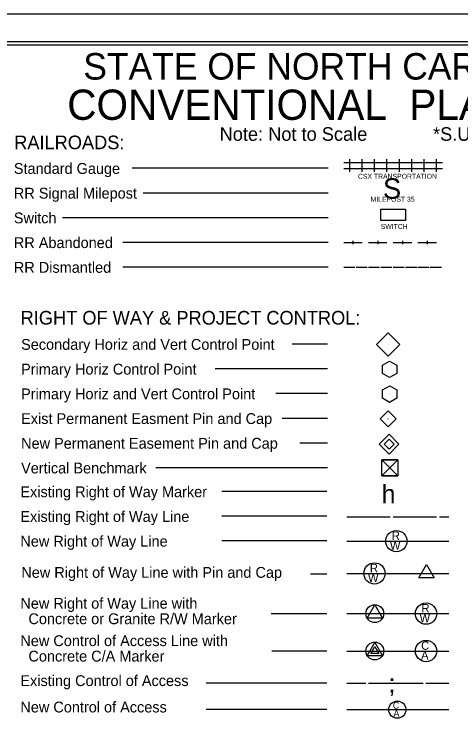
# Model space of a CAD drawing. Extents: x 2014488 to 2016172, y 399324 to 400424.
# Drawn here: x 2015050 to 2015411, y 399854 to 400424 of the extents above; entities that cross this region are included whole.
import ezdxf

# ---------------------------------------------------------------- set-up
doc = ezdxf.new("R2010")
doc.units = 0
for name, color, linetype in [('Prop ROW Permanent Easement CELL', 7, 'Continuous'), ('Sheet Plot Border Inside CELL', 7, 'Continuous'), ('Sheet Plot Border Outside CELL', 7, 'Continuous'), ('Sheet Symbology CELL', 7, 'Continuous'), ('Sheet Title CELL', 7, 'Continuous')]:
    doc.layers.add(name, color=color, linetype=linetype)

msp = doc.modelspace()

# ---------------------------------------------------------------- linework, layer by layer
at = {"layer": 'Prop ROW Permanent Easement CELL'}
msp.add_line((2015352.51, 400076.47), (2015352.51, 400076.47), dxfattribs=at)
for points in [[(2015352.51, 400084.52), (2015360.56, 400076.47), (2015352.51, 400068.42), (2015344.46, 400076.47)], [(2015352.51, 400080.5), (2015356.53, 400076.47), (2015352.51, 400072.45), (2015348.48, 400076.47)]]:
    msp.add_lwpolyline(points, close=True, dxfattribs=at)
at = {"layer": 'Sheet Plot Border Inside CELL'}
msp.add_lwpolyline([(2014500.85, 399346.86), (2016167.35, 399346.86), (2016167.35, 400401.96), (2014500.85, 400401.96)], close=True, dxfattribs=at)
at = {"layer": 'Sheet Plot Border Outside CELL'}
msp.add_lwpolyline([(2014487.85, 399324.41), (2016171.85, 399324.41), (2016171.85, 400424.41), (2014487.85, 400424.41)], close=True, dxfattribs=at)
at = {"layer": 'Sheet Symbology CELL'}
for p, q in [((2015315.85, 400304.44), (2015325.85, 400304.44)), ((2015320.85, 400296.94), (2015320.85, 400306.94)), ((2015325.85, 400304.44), (2015335.85, 400304.44)), ((2015330.85, 400296.94), (2015330.85, 400306.94)), ((2015335.85, 400304.44), (2015345.85, 400304.44)), ((2015340.85, 400296.94), (2015340.85, 400306.94)), ((2015345.85, 400304.44), (2015355.85, 400304.44)), ((2015350.85, 400296.94), (2015350.85, 400306.94)), ((2015355.85, 400304.44), (2015365.85, 400304.44)), ((2015360.85, 400296.94), (2015360.85, 400306.94)), ((2015365.85, 400304.44), (2015375.85, 400304.44)), ((2015370.85, 400296.94), (2015370.85, 400306.94)), ((2015375.85, 400304.44), (2015385.85, 400304.44)), ((2015380.85, 400296.94), (2015380.85, 400306.94)), ((2015385.85, 400304.44), (2015395.85, 400304.44)), ((2015390.85, 400296.94), (2015390.85, 400306.94)), ((2015303.45, 400299.68), (2015145.04, 400299.68)), ((2015315.85, 400299.44), (2015325.85, 400299.44)), ((2015325.85, 400299.44), (2015335.85, 400299.44)), ((2015335.85, 400299.44), (2015345.85, 400299.44)), ((2015345.85, 400299.44), (2015355.85, 400299.44)), ((2015355.85, 400299.44), (2015365.85, 400299.44)), ((2015365.85, 400299.44), (2015375.85, 400299.44)), ((2015375.85, 400299.44), (2015385.85, 400299.44)), ((2015385.85, 400299.44), (2015395.85, 400299.44)), ((2015303.45, 400279.68), (2015153.9, 400279.68)), ((2015303.45, 400259.68), (2015088.54, 400259.68)), ((2015303.45, 400239.68), (2015137.29, 400239.68)), ((2015315.85, 400239.68), (2015330.85, 400239.68)), ((2015323.35, 400240.93), (2015323.35, 400238.43)), ((2015335.85, 400239.68), (2015350.85, 400239.68)), ((2015343.35, 400240.93), (2015343.35, 400238.43)), ((2015355.85, 400239.68), (2015370.85, 400239.68)), ((2015363.35, 400240.93), (2015363.35, 400238.43)), ((2015375.85, 400239.68), (2015390.85, 400239.68)), ((2015383.35, 400240.93), (2015383.35, 400238.43)), ((2015303.45, 400219.68), (2015137.29, 400219.68)), ((2015303.45, 400219.68), (2015137.29, 400219.68)), ((2015315.85, 400219.68), (2015324.85, 400219.68)), ((2015325.85, 400219.68), (2015334.85, 400219.68)), ((2015335.85, 400219.68), (2015344.85, 400219.68)), ((2015345.85, 400219.68), (2015354.85, 400219.68)), ((2015355.85, 400219.68), (2015364.85, 400219.68)), ((2015365.85, 400219.68), (2015374.85, 400219.68)), ((2015375.85, 400219.68), (2015384.85, 400219.68)), ((2015385.85, 400219.68), (2015394.85, 400219.68)), ((2015302.91, 400157.4), (2015274.35, 400157.4)), ((2015302.91, 400137.4), (2015211.87, 400137.4)), ((2015302.91, 400117.4), (2015260.99, 400117.4)), ((2015302.91, 400097.4), (2015266.2, 400097.4)), ((2015302.91, 400077.4), (2015280.55, 400077.4)), ((2015302.91, 400057.4), (2015164.07, 400057.4)), ((2015302.31, 400038.21), (2015217.38, 400038.21)), ((2015302.31, 400018.21), (2015217.38, 400018.21)), ((2015318.34, 400017.63), (2015353.34, 400017.63)), ((2015355.84, 400017.63), (2015390.84, 400017.63)), ((2015393.34, 400017.63), (2015400.84, 400017.63)), ((2015302.31, 399998.21), (2015217.38, 399998.21)), ((2015318.34, 399998.08), (2015400.84, 399998.08)), ((2015302.31, 399971.36), (2015289.07, 399971.36)), ((2015318.34, 399971.96), (2015400.84, 399971.96)), ((2015382.79, 399971.96), (2015382.79, 399971.96)), ((2015302.31, 399939.32), (2015257.33, 399939.32)), ((2015318.34, 399939.46), (2015400.84, 399939.46)), ((2015341.04, 399939.46), (2015341.04, 399939.46)), ((2015302.31, 399909.08), (2015257.7, 399909.08)), ((2015318.34, 399909.21), (2015400.84, 399909.21)), ((2015341.04, 399909.21), (2015341.04, 399909.21)), ((2015302.31, 399883.13), (2015204.76, 399883.13)), ((2015318.34, 399883.13), (2015333.81, 399883.13)), ((2015335.81, 399883.13), (2015380.22, 399883.13)), ((2015382.22, 399883.13), (2015400.84, 399883.13)), ((2015302.31, 399861.78), (2015204.76, 399861.78)), ((2015318.34, 399861.78), (2015400.84, 399861.78))]:
    msp.add_line(p, q, dxfattribs=at)
for points in [[(2016154.85, 400399.41), (2014654.85, 400399.41), (2014654.85, 399350.43), (2016154.85, 399350.43)], [(2015345.85, 400266.64), (2015365.85, 400266.64), (2015365.85, 400257.54), (2015345.85, 400257.54)], [(2015376.54, 399968.36), (2015382.79, 399979.16), (2015389.04, 399968.36)], [(2015334.79, 399935.86), (2015341.04, 399946.66), (2015347.29, 399935.86)], [(2015334.79, 399905.61), (2015347.29, 399905.61), (2015341.04, 399916.41)], [(2015337.78, 399907.33), (2015341.04, 399912.98), (2015344.31, 399907.33)]]:
    msp.add_lwpolyline(points, close=True, dxfattribs=at)
for centre, radius in [((2015358.46, 399998.08), 8.61), ((2015340.76, 399971.96), 8.61), ((2015341.04, 399939.46), 7.2), ((2015382.44, 399939.46), 8.61), ((2015341.04, 399909.21), 7.2), ((2015382.44, 399909.21), 8.61), ((2015359.22, 399861.78), 6.89)]:
    msp.add_circle(centre, radius, dxfattribs=at)
at = {"layer": 'Sheet Title CELL'}
for p, q in [((2015351.72, 400157.06), (2015351.72, 400157.06)), ((2015353.02, 400137.06), (2015353.02, 400137.06)), ((2015353.02, 400117.05), (2015353.02, 400117.05)), ((2015351.75, 400097.02), (2015351.75, 400097.02)), ((2015353.27, 400057.45), (2015353.27, 400057.45))]:
    msp.add_line(p, q, dxfattribs=at)
for points in [[(2015342.31, 400157.09), (2015351.76, 400166.55), (2015361.24, 400157.08), (2015351.78, 400147.62)], [(2015347.19, 400120.43), (2015353.05, 400123.7), (2015358.92, 400120.48), (2015358.83, 400113.76), (2015352.96, 400110.35), (2015347.19, 400113.62)], [(2015345.25, 400097.02), (2015351.75, 400103.52), (2015358.24, 400097.02), (2015351.75, 400090.52)], [(2015346.77, 400063.92), (2015359.74, 400063.92), (2015359.74, 400050.95), (2015346.77, 400050.95)]]:
    msp.add_lwpolyline(points, close=True, dxfattribs=at)
for points in [[(2015353.02, 400130.4), (2015347.22, 400133.7), (2015347.22, 400140.35), (2015353.02, 400143.71), (2015358.82, 400140.42), (2015358.82, 400133.7), (2015353.02, 400130.4)], [(2015359.74, 400063.92), (2015346.77, 400050.95), (2015353.26, 400057.44), (2015359.74, 400050.95), (2015346.77, 400063.92)], [(2015353.26, 400057.44), (2015359.74, 400063.92), (2015346.77, 400063.92), (2015353.26, 400057.44)], [(2015353.26, 400057.44), (2015346.77, 400050.95), (2015359.74, 400050.95), (2015353.26, 400057.44)]]:
    msp.add_lwpolyline(points, dxfattribs=at)
msp.add_circle((2015351.75, 400097.02), 0.126, dxfattribs=at)

# ---------------------------------------------------------------- texts
at = {"layer": 'Sheet Symbology CELL'}
for s, height, p in [('STATE OF NORTH CAROLINA, DIVISION OF HIGHWAYS', 21.419, (2015105.41, 400371.45)), ('CONVENTIONAL  PLAN SHEET SYMBOLS', 24.4803, (2015092.46, 400338.88)), ('Note: Not to Scale', 11, (2015215.59, 400321.92)), ('*S.U.E. = Subsurface Utility Engineering', 11, (2015388.07, 400321.92)), ('RAILROADS:', 11, (2015049.57, 400315.13)), ('Standard Gauge', 8.75, (2015049.29, 400295.16)), ('CSX TRANSPORTATION', 4, (2015327.41, 400291.21)), ('S', 16.5, (2015347.61, 400275.06)), ('RR Signal Milepost', 8.75, (2015049.29, 400275.16)), ('MILEPOST 35', 4, (2015337.6, 400272.63)), ('Switch', 8.75, (2015049.29, 400255.16)), ('SWITCH', 4, (2015345.8, 400250.63)), ('RR Abandoned', 8.75, (2015049.29, 400235.16)), ('RR Dismantled', 8.75, (2015049.29, 400215.16)), ('RIGHT OF WAY & PROJECT CONTROL:', 11, (2015054.78, 400173.29)), ('Secondary Horiz and Vert Control Point', 8.75, (2015055.16, 400152.85)), ('Primary Horiz Control Point', 8.75, (2015055.16, 400132.85)), ('Primary Horiz and Vert Control Point', 8.75, (2015055.16, 400112.85)), ('Exist Permanent Easment Pin and Cap', 8.75, (2015055.16, 400092.85)), ('New Permanent Easement Pin and Cap', 8.75, (2015055.16, 400072.85)), ('Vertical Benchmark', 8.75, (2015055.16, 400052.85)), ('Existing Right of Way Marker', 8.75, (2015054.56, 400033.66)), ('h', 15, (2015346.53, 400028.64)), ('Existing Right of Way Line', 8.75, (2015054.56, 400013.66)), ('New Right of Way Line', 8.75, (2015054.56, 399993.66)), ('R', 6.75, (2015354.76, 399999.1)), ('W', 6.75, (2015353.22, 399991.15)), ('R', 6.75, (2015337.06, 399972.97)), ('New Right of Way Line with Pin and Cap', 8.75, (2015055.33, 399968.43)), ('W', 6.75, (2015335.52, 399965.02)), ('New Right of Way Line with', 8.75, (2015054.56, 399943.43)), ('R', 6.75, (2015378.73, 399940.47)), ('  Concrete or Granite R/W Marker', 8.75, (2015054.56, 399930.93)), ('W', 6.75, (2015377.19, 399932.52)), ('New Control of Access Line with', 8.75, (2015054.56, 399913.19)), ('C', 6.75, (2015378.48, 399910.23)), ('  Concrete C/A Marker', 8.75, (2015054.56, 399900.69)), ('A', 6.75, (2015378.42, 399902.28)), ('Existing Control of Access', 8.75, (2015054.56, 399880.87)), (';', 15, (2015352.09, 399875.63)), ('New Control of Access', 8.75, (2015054.56, 399859.52)), ('C', 5.4, (2015355.56, 399862.59)), ('A', 5.4, (2015356.09, 399856.11))]:
    msp.add_text(s, height=height, rotation=360, dxfattribs=at).set_placement(p)

doc.saveas('drawing.dxf')
